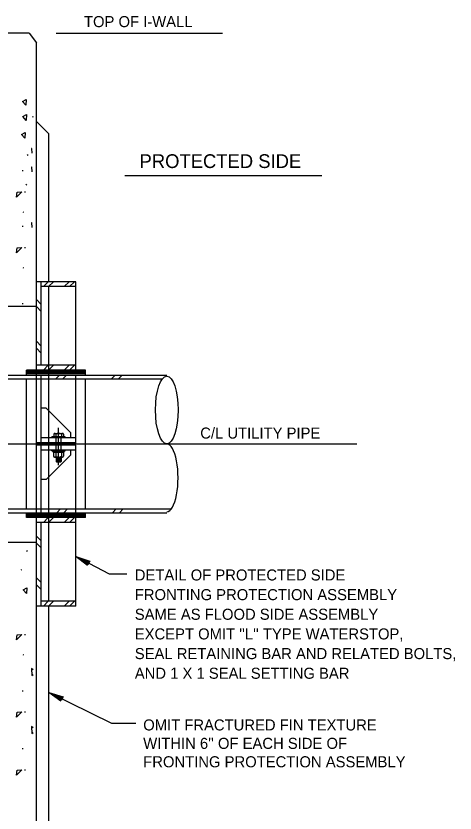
# Model space of a CAD drawing. Extents: x 22369.6 to 22389.4, y 22369.6 to 22386.
# Drawn here: x 22387.546 to 22389.406, y 22382.62 to 22386 of the extents above; entities that cross this region are included whole.
import ezdxf

# ---------------------------------------------------------------- set-up
doc = ezdxf.new("R2010")
doc.units = 0
for name, color, linetype in [('Level 1', 7, 'Continuous'), ('Level 10', 7, 'Continuous'), ('Level 2', 7, 'Continuous'), ('Level 3', 7, 'Continuous'), ('Level 4', 7, 'Continuous'), ('Level 44', 7, 'Continuous'), ('Level 50', 7, 'Continuous'), ('Level 7', 7, 'Continuous')]:
    doc.layers.add(name, color=color, linetype=linetype)

msp = doc.modelspace()

# ---------------------------------------------------------------- linework, layer by layer
at = {"layer": 'Level 1'}
for p, q in [((22387.716, 22385.9272), (22388.4201, 22385.9272)), ((22387.6622, 22384.8522), (22387.683, 22384.873)), ((22387.6843, 22384.8522), (22387.7051, 22384.873)), ((22387.7506, 22384.8522), (22387.7714, 22384.873)), ((22387.7727, 22384.8522), (22387.7935, 22384.873)), ((22387.6533, 22384.7765), (22387.6325, 22384.7973)), ((22387.6533, 22384.747), (22387.6325, 22384.7679)), ((22387.6533, 22384.5997), (22387.6325, 22384.6205)), ((22387.6533, 22384.5702), (22387.6325, 22384.5911)), ((22387.6622, 22384.498), (22387.683, 22384.5189)), ((22387.6843, 22384.498), (22387.7051, 22384.5189)), ((22387.7506, 22384.498), (22387.7714, 22384.5189)), ((22387.7727, 22384.498), (22387.7935, 22384.5189)), ((22387.8408, 22384.4928), (22387.5908, 22384.4928)), ((22387.8408, 22384.4876), (22387.5908, 22384.4876)), ((22387.8408, 22384.4824), (22387.5908, 22384.4824)), ((22387.7147, 22384.4616), (22387.7303, 22384.4772)), ((22387.7441, 22384.4616), (22387.7597, 22384.4772)), ((22387.9504, 22384.4616), (22387.966, 22384.4772)), ((22387.9798, 22384.4616), (22387.9954, 22384.4772)), ((22387.7101, 22384.23), (22387.7433, 22384.23)), ((22387.7263, 22384.0948), (22387.7263, 22384.2534)), ((22387.7547, 22384.2155), (22387.6974, 22384.2155)), ((22387.6974, 22384.2116), (22387.6974, 22384.2155)), ((22387.7058, 22384.2272), (22387.7058, 22384.2155)), ((22387.7144, 22384.2273), (22387.7144, 22384.2155)), ((22387.7159, 22384.1595), (22387.7159, 22384.2116)), ((22387.7367, 22384.1595), (22387.7367, 22384.2116)), ((22387.7391, 22384.2273), (22387.7391, 22384.2155)), ((22387.7475, 22384.2272), (22387.7475, 22384.2155)), ((22387.7547, 22384.2116), (22387.7547, 22384.2155)), ((22386.0985, 22384.1855), (22388.9892, 22384.1855)), ((22387.6325, 22384.1881), (22387.7991, 22384.1881)), ((22387.6325, 22384.1829), (22387.7991, 22384.1829)), ((22387.7991, 22384.1829), (22387.7991, 22384.1881)), ((22387.6977, 22384.1556), (22387.6977, 22384.1595)), ((22387.6977, 22384.1556), (22387.755, 22384.1556)), ((22387.7029, 22384.1504), (22387.7029, 22384.1556)), ((22387.7029, 22384.1504), (22387.7498, 22384.1504)), ((22387.7055, 22384.1504), (22387.7055, 22384.1337)), ((22387.7097, 22384.1296), (22387.743, 22384.1296)), ((22387.7141, 22384.1504), (22387.7141, 22384.1337)), ((22387.7159, 22384.1296), (22387.7159, 22384.1108)), ((22387.7367, 22384.1296), (22387.7367, 22384.1109)), ((22387.7387, 22384.1504), (22387.7387, 22384.1337)), ((22387.7472, 22384.1504), (22387.7472, 22384.1337)), ((22387.7498, 22384.1504), (22387.7498, 22384.1556)), ((22387.755, 22384.1556), (22387.755, 22384.1595)), ((22387.7159, 22384.1274), (22387.7367, 22384.1274)), ((22387.7159, 22384.1233), (22387.7367, 22384.1233)), ((22387.7159, 22384.1191), (22387.7367, 22384.1191)), ((22387.7159, 22384.1149), (22387.7367, 22384.1149)), ((22387.7159, 22384.1108), (22387.717, 22384.1097)), ((22387.7159, 22384.1108), (22387.7367, 22384.1108)), ((22387.717, 22384.1097), (22387.7357, 22384.1097)), ((22387.7211, 22384.1253), (22387.7321, 22384.1253)), ((22387.7211, 22384.1212), (22387.7321, 22384.1212)), ((22387.7211, 22384.117), (22387.7321, 22384.117)), ((22387.7211, 22384.1128), (22387.7321, 22384.1128)), ((22387.7367, 22384.1109), (22387.7357, 22384.1097)), ((22387.7191, 22383.8939), (22387.7347, 22383.9095)), ((22387.7485, 22383.8939), (22387.7642, 22383.9095)), ((22387.9548, 22383.8939), (22387.9704, 22383.9095)), ((22387.9842, 22383.8939), (22387.9999, 22383.9095)), ((22387.8408, 22383.8887), (22387.5908, 22383.8887)), ((22387.8408, 22383.8834), (22387.5908, 22383.8834)), ((22387.8408, 22383.8782), (22387.5908, 22383.8782)), ((22387.6622, 22383.8522), (22387.683, 22383.873)), ((22387.6843, 22383.8522), (22387.7051, 22383.873)), ((22387.7506, 22383.8522), (22387.7714, 22383.873)), ((22387.7727, 22383.8522), (22387.7935, 22383.873)), ((22387.6533, 22383.774), (22387.6325, 22383.7948)), ((22387.6533, 22383.7445), (22387.6325, 22383.7653)), ((22387.6533, 22383.5972), (22387.6325, 22383.618)), ((22387.6533, 22383.5677), (22387.6325, 22383.5886)), ((22387.6622, 22383.498), (22387.683, 22383.5189)), ((22387.6843, 22383.498), (22387.7051, 22383.5189)), ((22387.7506, 22383.498), (22387.7714, 22383.5189)), ((22387.7727, 22383.498), (22387.7935, 22383.5189))]:
    msp.add_line(p, q, dxfattribs=at)
for centre, radius, start, end in [((22387.7101, 22384.2254), 0.00469, 24.0009, 156.8325), ((22387.7266, 22384.2016), 0.0285, 64.116, 115.4481), ((22387.7433, 22384.2255), 0.00456, 22.8005, 157.625), ((22387.7097, 22384.1338), 0.00422, 180.5659, 359.4341), ((22387.7264, 22384.1498), 0.0203, 232.4343, 307.5657), ((22387.743, 22384.1338), 0.00421, 180.4975, 359.5025)]:
    msp.add_arc(centre, radius, start, end, dxfattribs=at)
msp.add_ellipse((22388.1846, 22384.3293), major_axis=(0, 0.1438), ratio=0.333333, dxfattribs=at)
msp.add_ellipse((22388.1846, 22384.0418), major_axis=(0, -0.1438), ratio=0.333333, start_param=0, end_param=3.141593, dxfattribs=at)
at = {"layer": 'Level 10'}
msp.add_line((22388.841, 22385.3226), (22388.0071, 22385.3226), dxfattribs=at)
at = {"layer": 'Level 2'}
for p, q in [((22387.7991, 22384.873), (22387.6325, 22384.873)), ((22387.6325, 22384.498), (22387.6325, 22384.873)), ((22387.6533, 22384.5189), (22387.6533, 22384.873)), ((22387.7991, 22384.498), (22387.7991, 22384.873)), ((22387.7991, 22384.8522), (22387.6533, 22384.8522)), ((22387.7991, 22384.5189), (22387.6325, 22384.5189)), ((22386.4554, 22384.4772), (22388.1846, 22384.4772)), ((22387.8408, 22384.498), (22387.5908, 22384.498)), ((22387.5908, 22384.4772), (22387.5908, 22384.498)), ((22387.6325, 22384.1907), (22387.6325, 22384.4772)), ((22387.6533, 22384.1907), (22387.6533, 22384.4772)), ((22387.7991, 22384.1907), (22387.7991, 22384.4772)), ((22387.8408, 22384.4772), (22387.8408, 22384.498)), ((22386.4366, 22384.4616), (22388.1658, 22384.4616)), ((22387.5908, 22383.9095), (22387.5908, 22384.4616)), ((22387.8408, 22383.9095), (22387.8408, 22384.4616)), ((22387.6742, 22384.3366), (22387.6534, 22384.3366)), ((22387.7784, 22384.2324), (22387.6742, 22384.3366)), ((22387.7784, 22384.2116), (22387.7784, 22384.2324)), ((22387.7991, 22384.2116), (22387.6533, 22384.2116)), ((22387.7991, 22384.1907), (22387.6325, 22384.1907)), ((22387.7991, 22384.1803), (22387.6325, 22384.1803)), ((22387.6325, 22383.8939), (22387.6325, 22384.1803)), ((22387.6533, 22383.8939), (22387.6533, 22384.1803)), ((22387.7991, 22383.8939), (22387.7991, 22384.1803)), ((22387.7991, 22384.1595), (22387.6533, 22384.1595)), ((22387.7784, 22384.1387), (22387.6742, 22384.0345)), ((22387.7784, 22384.1387), (22387.7784, 22384.1595)), ((22387.6742, 22384.0345), (22387.6534, 22384.0345)), ((22386.4554, 22383.8939), (22388.1846, 22383.8939)), ((22386.4741, 22383.9095), (22388.2033, 22383.9095)), ((22387.5908, 22383.873), (22387.5908, 22383.8939)), ((22387.8408, 22383.873), (22387.8408, 22383.8939)), ((22387.8408, 22383.873), (22387.5908, 22383.873)), ((22387.6325, 22383.498), (22387.6325, 22383.873)), ((22387.7991, 22383.498), (22387.7991, 22383.873)), ((22387.7991, 22383.8522), (22387.6325, 22383.8522)), ((22387.6533, 22383.498), (22387.6533, 22383.8522)), ((22387.7991, 22383.7078), (22387.7991, 22383.7078)), ((22387.8145, 22383.6997), (22387.8145, 22383.6997)), ((22387.7991, 22383.498), (22387.6325, 22383.498)), ((22387.7991, 22383.5189), (22387.6533, 22383.5189)), ((22387.6849, 22383.1322), (22387.6849, 22383.1322)), ((22387.7004, 22383.1245), (22387.7004, 22383.1245))]:
    msp.add_line(p, q, dxfattribs=at)
for points in [[(22388.015, 22383.6331), (22387.9414, 22383.6331), (22387.7991, 22383.7078)], [(22387.8495, 22383.6697), (22387.7991, 22383.7078), (22387.8591, 22383.688), (22387.8509, 22383.6723), (22387.8145, 22383.6997), (22387.8552, 22383.6862), (22387.85, 22383.6762), (22387.8292, 22383.692), (22387.8513, 22383.6845), (22387.8491, 22383.6804), (22387.8446, 22383.6839)], [(22388.0532, 22382.9994), (22387.9523, 22382.9994), (22387.6849, 22383.1322)], [(22387.7361, 22383.0952), (22387.6849, 22383.1322), (22387.7453, 22383.1138), (22387.7374, 22383.0979), (22387.7004, 22383.1245), (22387.7414, 22383.112), (22387.7364, 22383.1018), (22387.7153, 22383.1171), (22387.7375, 22383.1102), (22387.7355, 22383.106), (22387.7308, 22383.1094)]]:
    msp.add_lwpolyline(points, dxfattribs=at)
at = {"layer": 'Level 3'}
msp.add_line((22387.6742, 22384.0345), (22387.6742, 22384.0345), dxfattribs=at)
at = {"layer": 'Level 44'}
for p, q in [((22387.6145, 22385.5741), (22387.6185, 22385.5721)), ((22387.5932, 22385.4101), (22387.597, 22385.4124)), ((22387.5721, 22385.3443), (22387.5766, 22385.3443)), ((22387.5875, 22385.2862), (22387.5915, 22385.2842)), ((22387.5818, 22385.2541), (22387.5861, 22385.2541)), ((22387.5752, 22385.1698), (22387.5785, 22385.1685)), ((22387.5721, 22385.108), (22387.5766, 22385.108)), ((22387.5818, 22385.0179), (22387.5861, 22385.0179)), ((22387.5752, 22384.9335), (22387.5785, 22384.9323)), ((22387.5721, 22384.7801), (22387.5766, 22384.7801)), ((22387.5908, 22383.7309), (22387.5945, 22383.7332)), ((22387.5673, 22383.6509), (22387.5711, 22383.6531)), ((22387.5818, 22383.3769), (22387.5861, 22383.3769)), ((22387.5752, 22383.2926), (22387.5785, 22383.2914)), ((22387.5721, 22383.1392), (22387.5766, 22383.1392)), ((22387.5818, 22383.049), (22387.5861, 22383.049)), ((22387.5721, 22382.8936), (22387.5766, 22382.8936)), ((22387.5818, 22382.8034), (22387.5861, 22382.8034))]:
    msp.add_line(p, q, dxfattribs=at)
for points in [[(22387.5874, 22385.6214), (22387.5731, 22385.6374), (22387.5891, 22385.6459)], [(22387.5889, 22385.5569), (22387.5747, 22385.5729), (22387.5906, 22385.5814)], [(22387.5835, 22385.4812), (22387.5693, 22385.4972), (22387.5852, 22385.5057)], [(22387.5506, 22385.253), (22387.5706, 22385.2541), (22387.5489, 22385.2319)], [(22387.5506, 22385.0168), (22387.5706, 22385.0179), (22387.5489, 22384.9957)], [(22387.5908, 22383.5512), (22387.5765, 22383.5672), (22387.5925, 22383.5757)], [(22387.5506, 22383.3759), (22387.5706, 22383.3769), (22387.5489, 22383.3548)], [(22387.5506, 22383.0479), (22387.5706, 22383.049), (22387.5489, 22383.0269)], [(22387.5506, 22382.8023), (22387.5706, 22382.8034), (22387.5489, 22382.7812)]]:
    msp.add_lwpolyline(points, close=True, dxfattribs=at)
for points in [[(22387.6133, 22385.4372), (22387.6121, 22385.4382), (22387.6133, 22385.4175)], [(22387.6133, 22385.3593), (22387.6121, 22385.3603), (22387.6133, 22385.3396)], [(22387.6133, 22385.123), (22387.6121, 22385.124), (22387.6133, 22385.1034)], [(22387.6186, 22383.2273), (22387.6121, 22383.2331), (22387.6138, 22383.2036)], [(22387.6138, 22383.2036), (22387.6186, 22383.2081)], [(22387.6186, 22382.9816), (22387.6121, 22382.9875), (22387.6138, 22382.958)], [(22387.6138, 22382.958), (22387.6186, 22382.9625)]]:
    msp.add_lwpolyline(points, dxfattribs=at)
at = {"layer": 'Level 50'}
msp.add_line((22387.7472, 22384.1337), (22387.7472, 22384.1337), dxfattribs=at)
at = {"layer": 'Level 7'}
for p, q in [((22387.6012, 22385.9272), (22387.1637, 22385.9272)), ((22387.6012, 22385.9272), (22387.6325, 22385.8855)), ((22387.6325, 22384.4772), (22387.6325, 22385.8855)), ((22387.6325, 22385.5522), (22387.6846, 22385.5001)), ((22387.6846, 22384.873), (22387.6846, 22385.5001)), ((22387.6846, 22383.5189), (22387.6846, 22384.8522)), ((22387.1325, 22384.7689), (22387.6325, 22384.7689)), ((22387.6325, 22383.9095), (22387.6325, 22384.4616)), ((22387.6325, 22382.184), (22387.6325, 22383.8939)), ((22387.1325, 22383.7689), (22387.6325, 22383.7689)), ((22387.6846, 22382.3611), (22387.6846, 22383.498))]:
    msp.add_line(p, q, dxfattribs=at)

# ---------------------------------------------------------------- texts
at = {"layer": 'Level 10'}
msp.add_text('PROTECTED SIDE', height=0.058333, dxfattribs=at).set_placement((22388.0693, 22385.3551))
at = {"layer": 'Level 4'}
for s, p in [('TOP OF I-WALL', (22387.834, 22385.9523)), ('C/L UTILITY PIPE', (22388.3264, 22384.2079)), ('DETAIL OF PROTECTED SIDE', (22388.0492, 22383.6064)), ('FRONTING PROTECTION ASSEMBLY', (22388.0492, 22383.523)), ('SAME AS FLOOD SIDE ASSEMBLY', (22388.0492, 22383.4397)), ("EXCEPT OMIT ''L'' TYPE WATERSTOP,", (22388.0492, 22383.3564)), ('SEAL RETAINING BAR AND RELATED BOLTS,', (22388.0492, 22383.273)), ('AND 1 X 1 SEAL SETTING BAR', (22388.0492, 22383.1897)), ('OMIT FRACTURED FIN TEXTURE', (22388.0849, 22382.9706)), ("WITHIN 6'' OF EACH SIDE OF", (22388.0849, 22382.8925)), ('FRONTING PROTECTION ASSEMBLY', (22388.0849, 22382.8144))]:
    msp.add_text(s, height=0.046875, dxfattribs=at).set_placement(p)

doc.saveas('drawing.dxf')
